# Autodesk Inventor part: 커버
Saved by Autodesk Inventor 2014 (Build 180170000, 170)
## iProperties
Created: 2026-09
Part Number: 커버
Material: 일반
Document SubType Name: Modeling
Designer: dg
Density: 1 g/cm^3
Appearance: 기본값
Author: dg
Author: jhkim
Creation Date: 2026-08-26
Sending System: Autodesk Inventor 2027
Preprocessor: ST-DEVELOPER v20.1
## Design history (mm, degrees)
node "커버1"
node "솔리드2"
node "기준1"
